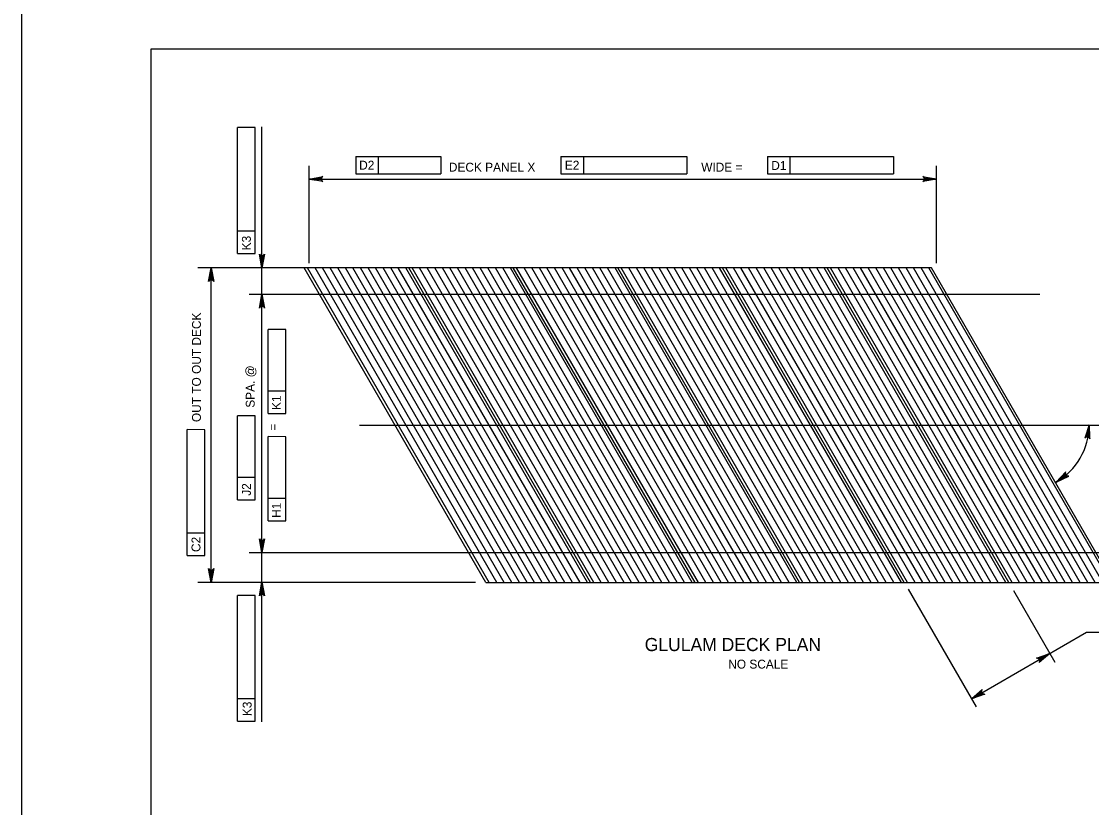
# Model space of a CAD drawing. Extents: x -13 to 81, y -176 to 0.
# Drawn here: x 34 to 48.46, y -121 to -110.38 of the extents above; entities that cross this region are included whole.
import ezdxf

# ---------------------------------------------------------------- set-up
doc = ezdxf.new("R2010")
doc.units = 0
for name, color, linetype in [('Level 1', 7, 'Continuous'), ('Level 2', 7, 'Continuous'), ('Level 4', 7, 'Continuous'), ('Level 5', 7, 'Continuous'), ('Level 63', 7, 'Continuous')]:
    doc.layers.add(name, color=color, linetype=linetype)

msp = doc.modelspace()

# ---------------------------------------------------------------- linework, layer by layer
at = {"layer": 'Level 1'}
msp.add_lwpolyline([(35.75, -131.25), (67.25, -131.25), (67.25, -110.75), (35.75, -110.75)], close=True, dxfattribs=at)
at = {"layer": 'Level 2'}
for p, q in [((46.299, -113.704), (37.821, -113.704)), ((40.275, -117.956), (37.821, -113.704)), ((41.689, -117.956), (39.234, -113.704)), ((43.102, -117.956), (40.647, -113.704)), ((44.515, -117.956), (42.06, -113.704)), ((45.928, -117.956), (43.473, -113.704)), ((47.341, -117.956), (44.886, -113.704)), ((48.754, -117.956), (46.299, -113.704)), ((40.275, -117.956), (48.754, -117.956))]:
    msp.add_line(p, q, dxfattribs=at)
at = {"layer": 'Level 4'}
for p, q in [((37.158, -111.81), (36.922, -111.809)), ((36.922, -113.208), (36.922, -111.809)), ((37.158, -113.51), (37.158, -111.81)), ((37.25, -119.839), (37.25, -111.8)), ((38.52, -112.2), (38.822, -112.2)), ((38.52, -112.2), (38.52, -112.436)), ((38.822, -112.2), (38.822, -112.436)), ((38.822, -112.2), (39.667, -112.2)), ((39.667, -112.2), (39.667, -112.436)), ((41.291, -112.2), (41.593, -112.2)), ((41.291, -112.2), (41.291, -112.436)), ((41.593, -112.2), (41.593, -112.436)), ((41.593, -112.2), (42.992, -112.2)), ((42.992, -112.2), (42.992, -112.436)), ((44.082, -112.2), (44.082, -112.436)), ((44.082, -112.2), (44.385, -112.2)), ((44.385, -112.2), (44.385, -112.436)), ((44.385, -112.2), (45.783, -112.2)), ((45.783, -112.2), (45.783, -112.436)), ((37.888, -113.641), (37.888, -112.325)), ((46.367, -113.641), (46.367, -112.325)), ((38.52, -112.436), (39.667, -112.436)), ((41.291, -112.436), (42.992, -112.436)), ((44.082, -112.436), (45.783, -112.436)), ((37.888, -112.505), (46.367, -112.505)), ((36.922, -113.51), (36.922, -113.208)), ((37.158, -113.208), (36.922, -113.208)), ((36.922, -113.51), (37.158, -113.51)), ((40.504, -113.704), (36.383, -113.704)), ((36.563, -117.956), (36.563, -113.704)), ((37.079, -114.062), (47.762, -114.062)), ((37.572, -114.539), (37.336, -114.538)), ((37.336, -115.379), (37.336, -114.538)), ((37.572, -115.675), (37.572, -114.539)), ((37.572, -115.372), (37.336, -115.372)), ((37.336, -115.674), (37.336, -115.379)), ((37.336, -115.674), (37.572, -115.675)), ((37.158, -115.705), (36.922, -115.705)), ((36.922, -116.539), (36.922, -115.705)), ((37.158, -116.842), (37.158, -115.705)), ((36.477, -115.893), (36.241, -115.892)), ((36.241, -117.291), (36.241, -115.892)), ((36.477, -117.593), (36.477, -115.893)), ((38.568, -115.83), (48.782, -115.83)), ((37.572, -115.988), (37.336, -115.987)), ((37.336, -116.821), (37.336, -115.987)), ((37.572, -117.124), (37.572, -115.988)), ((36.922, -116.841), (36.922, -116.539)), ((37.158, -116.539), (36.922, -116.539)), ((36.922, -116.841), (37.158, -116.842)), ((37.336, -117.124), (37.336, -116.821)), ((37.572, -116.821), (37.336, -116.821)), ((37.336, -117.124), (37.572, -117.124)), ((36.241, -117.593), (36.241, -117.291)), ((36.477, -117.291), (36.241, -117.291)), ((37.079, -117.553), (49.777, -117.553)), ((36.241, -117.593), (36.477, -117.593)), ((40.136, -117.956), (36.383, -117.956)), ((37.158, -118.133), (36.922, -118.133)), ((36.922, -119.531), (36.922, -118.133)), ((37.158, -119.834), (37.158, -118.133)), ((45.981, -118.048), (46.9, -119.638)), ((47.404, -118.064), (47.964, -119.035)), ((46.837, -119.529), (48.392, -118.631)), ((48.392, -118.631), (50.61, -118.631)), ((36.922, -119.834), (36.922, -119.531)), ((37.158, -119.531), (36.922, -119.531)), ((36.922, -119.834), (37.158, -119.834))]:
    msp.add_line(p, q, dxfattribs=at)
for points in [[(37.888, -112.505), (38.075, -112.47), (38.06, -112.48), (38.053, -112.492), (38.051, -112.505), (38.053, -112.517), (38.06, -112.53), (38.075, -112.539), (37.888, -112.505), (38.06, -112.53), (38.053, -112.517), (37.888, -112.505), (38.051, -112.505), (38.053, -112.492), (37.888, -112.505), (38.06, -112.48)], [(46.367, -112.505), (46.18, -112.539), (46.195, -112.53), (46.202, -112.517), (46.204, -112.505), (46.202, -112.492), (46.195, -112.48), (46.18, -112.47), (46.367, -112.505), (46.195, -112.48), (46.202, -112.492), (46.367, -112.505), (46.204, -112.505), (46.202, -112.517), (46.367, -112.505), (46.195, -112.53)], [(37.25, -113.708), (37.215, -113.522), (37.225, -113.536), (37.238, -113.544), (37.25, -113.546), (37.263, -113.544), (37.275, -113.536), (37.285, -113.522), (37.25, -113.708), (37.275, -113.536), (37.263, -113.544), (37.25, -113.708), (37.25, -113.546), (37.238, -113.544), (37.25, -113.708), (37.225, -113.536)], [(36.563, -113.704), (36.598, -113.89), (36.588, -113.876), (36.576, -113.868), (36.563, -113.866), (36.551, -113.868), (36.538, -113.876), (36.528, -113.89), (36.563, -113.704), (36.538, -113.876), (36.551, -113.868), (36.563, -113.704), (36.563, -113.866), (36.576, -113.868), (36.563, -113.704), (36.588, -113.876)], [(37.25, -114.062), (37.285, -114.249), (37.275, -114.234), (37.263, -114.227), (37.25, -114.225), (37.238, -114.227), (37.225, -114.234), (37.215, -114.249), (37.25, -114.062), (37.225, -114.234), (37.238, -114.227), (37.25, -114.062), (37.25, -114.225), (37.263, -114.227), (37.25, -114.062), (37.275, -114.234)], [(48.427, -115.829), (48.369, -116.009), (48.381, -115.996), (48.394, -115.991), (48.407, -115.99), (48.419, -115.994), (48.431, -116.003), (48.439, -116.018), (48.427, -115.829), (48.431, -116.003), (48.419, -115.994), (48.427, -115.829), (48.407, -115.99), (48.394, -115.991), (48.427, -115.829), (48.381, -115.996)], [(47.982, -116.602), (48.153, -116.52), (48.136, -116.521), (48.122, -116.515), (48.113, -116.506), (48.108, -116.495), (48.106, -116.48), (48.112, -116.464), (47.982, -116.602), (48.106, -116.48), (48.108, -116.495), (47.982, -116.602), (48.113, -116.506), (48.122, -116.515), (47.982, -116.602), (48.136, -116.521)], [(37.25, -117.553), (37.215, -117.367), (37.225, -117.381), (37.238, -117.389), (37.25, -117.391), (37.263, -117.389), (37.275, -117.381), (37.285, -117.367), (37.25, -117.553), (37.275, -117.381), (37.263, -117.389), (37.25, -117.553), (37.25, -117.391), (37.238, -117.389), (37.25, -117.553), (37.225, -117.381)], [(36.563, -117.956), (36.528, -117.769), (36.538, -117.784), (36.551, -117.791), (36.563, -117.793), (36.576, -117.791), (36.588, -117.784), (36.598, -117.769), (36.563, -117.956), (36.588, -117.784), (36.576, -117.791), (36.563, -117.956), (36.563, -117.793), (36.551, -117.791), (36.563, -117.956), (36.538, -117.784)], [(37.25, -117.951), (37.285, -118.138), (37.275, -118.123), (37.263, -118.116), (37.25, -118.114), (37.238, -118.116), (37.225, -118.123), (37.215, -118.138), (37.25, -117.951), (37.225, -118.123), (37.238, -118.116), (37.25, -117.951), (37.25, -118.114), (37.263, -118.116), (37.25, -117.951), (37.275, -118.123)], [(47.897, -118.917), (47.753, -119.041), (47.76, -119.025), (47.76, -119.01), (47.756, -118.998), (47.748, -118.989), (47.735, -118.982), (47.718, -118.98), (47.897, -118.917), (47.735, -118.982), (47.748, -118.989), (47.897, -118.917), (47.756, -118.998), (47.76, -119.01), (47.897, -118.917), (47.76, -119.025)], [(46.837, -119.529), (46.981, -119.406), (46.974, -119.422), (46.973, -119.436), (46.978, -119.448), (46.986, -119.458), (46.999, -119.465), (47.016, -119.466), (46.837, -119.529), (46.999, -119.465), (46.986, -119.458), (46.837, -119.529), (46.978, -119.448), (46.973, -119.436), (46.837, -119.529), (46.974, -119.422)]]:
    msp.add_lwpolyline(points, dxfattribs=at)
msp.add_arc((47.536, -115.83), 0.891, 299.9994, 0.0006, dxfattribs=at)
at = {"layer": 'Level 5'}
for p, q in [((40.32, -117.956), (37.866, -113.704)), ((40.423, -117.956), (37.968, -113.704)), ((40.525, -117.956), (38.07, -113.704)), ((40.627, -117.956), (38.172, -113.704)), ((40.73, -117.956), (38.275, -113.704)), ((40.832, -117.956), (38.377, -113.704)), ((40.934, -117.956), (38.479, -113.704)), ((41.036, -117.956), (38.582, -113.704)), ((41.139, -117.956), (38.684, -113.704)), ((41.241, -117.956), (38.786, -113.704)), ((41.343, -117.956), (38.889, -113.704)), ((41.446, -117.956), (38.991, -113.704)), ((41.548, -117.956), (39.093, -113.704)), ((41.65, -117.956), (39.195, -113.704)), ((41.734, -117.956), (39.279, -113.704)), ((41.836, -117.956), (39.381, -113.704)), ((41.938, -117.956), (39.483, -113.704)), ((42.041, -117.956), (39.586, -113.704)), ((42.143, -117.956), (39.688, -113.704)), ((42.245, -117.956), (39.79, -113.704)), ((42.347, -117.956), (39.892, -113.704)), ((42.45, -117.956), (39.995, -113.704)), ((42.552, -117.956), (40.097, -113.704)), ((42.654, -117.956), (40.199, -113.704)), ((42.756, -117.956), (40.302, -113.704)), ((42.859, -117.956), (40.404, -113.704)), ((42.961, -117.956), (40.506, -113.704)), ((43.063, -117.956), (40.608, -113.704)), ((43.147, -117.956), (40.692, -113.704)), ((43.249, -117.956), (40.794, -113.704)), ((43.351, -117.956), (40.896, -113.704)), ((43.454, -117.956), (40.999, -113.704)), ((43.556, -117.956), (41.101, -113.704)), ((43.658, -117.956), (41.203, -113.704)), ((43.761, -117.956), (41.306, -113.704)), ((43.863, -117.956), (41.408, -113.704)), ((43.965, -117.956), (41.51, -113.704)), ((44.067, -117.956), (41.612, -113.704)), ((44.17, -117.956), (41.715, -113.704)), ((44.272, -117.956), (41.817, -113.704)), ((44.374, -117.956), (41.919, -113.704)), ((44.477, -117.956), (42.022, -113.704)), ((44.56, -117.956), (42.105, -113.704)), ((44.662, -117.956), (42.207, -113.704)), ((44.764, -117.956), (42.31, -113.704)), ((44.867, -117.956), (42.412, -113.704)), ((44.969, -117.956), (42.514, -113.704)), ((45.071, -117.956), (42.617, -113.704)), ((45.174, -117.956), (42.719, -113.704)), ((45.276, -117.956), (42.821, -113.704)), ((45.378, -117.956), (42.923, -113.704)), ((45.48, -117.956), (43.026, -113.704)), ((45.583, -117.956), (43.128, -113.704)), ((45.685, -117.956), (43.23, -113.704)), ((45.787, -117.956), (43.332, -113.704)), ((45.89, -117.956), (43.435, -113.704)), ((45.973, -117.956), (43.518, -113.704)), ((46.075, -117.956), (43.62, -113.704)), ((46.178, -117.956), (43.723, -113.704)), ((46.28, -117.956), (43.825, -113.704)), ((46.382, -117.956), (43.927, -113.704)), ((46.484, -117.956), (44.03, -113.704)), ((46.587, -117.956), (44.132, -113.704)), ((46.689, -117.956), (44.234, -113.704)), ((46.791, -117.956), (44.336, -113.704)), ((46.894, -117.956), (44.439, -113.704)), ((46.996, -117.956), (44.541, -113.704)), ((47.098, -117.956), (44.643, -113.704)), ((47.2, -117.956), (44.746, -113.704)), ((47.303, -117.956), (44.848, -113.704)), ((47.386, -117.956), (44.931, -113.704)), ((47.488, -117.956), (45.034, -113.704)), ((47.591, -117.956), (45.136, -113.704)), ((47.693, -117.956), (45.238, -113.704)), ((47.795, -117.956), (45.34, -113.704)), ((47.898, -117.956), (45.443, -113.704)), ((48, -117.956), (45.545, -113.704)), ((48.102, -117.956), (45.647, -113.704)), ((48.204, -117.956), (45.75, -113.704)), ((48.307, -117.956), (45.852, -113.704)), ((48.409, -117.956), (45.954, -113.704)), ((48.511, -117.956), (46.056, -113.704)), ((48.614, -117.956), (46.159, -113.704)), ((48.716, -117.956), (46.261, -113.704))]:
    msp.add_line(p, q, dxfattribs=at)
at = {"layer": 'Level 63'}
msp.add_lwpolyline([(34, -132), (68, -132), (68, -110), (34, -110)], close=True, dxfattribs=at)

# ---------------------------------------------------------------- texts
at = {"layer": 'Level 4'}
for s, rotation, p in [('D2', 359.9382, (38.564, -112.378)), ('E2', 359.9382, (41.343, -112.378)), ('D1', 359.9382, (44.132, -112.382)), ('K3', 89.9382, (37.1, -113.469)), ('OUT TO OUT DECK', 90, (36.425, -115.79)), ('SPA. @', 90, (37.152, -115.596)), ('K1', 89.9382, (37.505, -115.626)), ('=', 90, (37.461, -115.906)), ('J2', 89.9382, (37.1, -116.786)), ('H1', 89.9382, (37.505, -117.084)), ('C2', 89.9382, (36.419, -117.546)), ('K3', 89.9382, (37.11, -119.764))]:
    msp.add_text(s, height=0.12, rotation=rotation, dxfattribs=at).set_placement(p)
for s, height, p in [('DECK PANEL X', 0.12, (39.776, -112.405)), ('WIDE =', 0.12, (43.186, -112.405)), ('GLULAM DECK PLAN', 0.17717, (42.422, -118.885)), ('NO SCALE', 0.12, (43.551, -119.121))]:
    msp.add_text(s, height=height, dxfattribs=at).set_placement(p)

doc.saveas('drawing.dxf')
